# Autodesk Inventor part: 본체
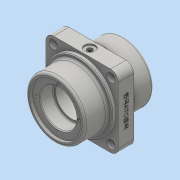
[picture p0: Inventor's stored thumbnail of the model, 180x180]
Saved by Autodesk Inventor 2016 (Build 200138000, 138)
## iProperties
Created: 2023-10
Part Number: 본체
Material: 일반
Document SubType Name: Modeling
Designer: pc-2
Density: 1 g/cm^3
Appearance: 기본값
Author: pc-2
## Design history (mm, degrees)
sketch "스케치1"
  geometry: L1 (47, -47)-(-47, -47); L2 (-47, -47)-(-47, 47); L3 (-47, 47)-(47, 47); L4 (47, 47)-(47, -47); L5 (47, -47)-(-47, 47); L6 (-47, -47)-(47, 47); 1 further point
  constraints: 12 end point, 2 midpoint, 2 parallel, 1 horizontal, 1 perpendicular
  dimensions: "d0" = 94 distance of L2.end L3.end; "d1" = 94 distance of L3.end L1.start
extrude "돌출1" new body sketch "스케치1" stored distance "d2" = 20; taper "d3" = 0 deg
sketch "스케치2"
  geometry: C1 r 44 at (0, 0); 1 further point
  constraints: 1 centre point, 1 coincident
  dimensions: "d4" = 88 diameter of C1
extrude "돌출2" join sketch "스케치2" distance "d5" = 5; taper "d6" = 0 deg
sketch "스케치3"
  geometry: C1 r 38 at (0, 0); 1 further point
  constraints: 1 centre point, 1 coincident
  dimensions: "d7" = 76 diameter of C1
extrude "돌출3" join sketch "스케치3" distance "d8" = 30; taper "d9" = 0 deg
hole "구멍1" diameter "d12" = 66; stored, may be unused: countersink angle "d16" = 90 deg, drill point angle "d18" = 0 deg; dims "d10" = 10, "d11" = 10, "d13" = 6, "d14" = 4, "d15" = 2, "d17" = 4
hole "구멍2" diameter "d21" = 47; stored, may be unused: countersink angle "d25" = 90 deg, drill point angle "d27" = 0 deg; dims "d19" = 10, "d20" = 10, "d22" = 6, "d23" = 4, "d24" = 2, "d26" = 17
hole "구멍3" diameter "d30" = 41; stored, may be unused: countersink angle "d34" = 90 deg, drill point angle "d36" = 0 deg; dims "d28" = 10, "d29" = 10, "d31" = 6, "d32" = 4, "d33" = 2, "d35" = 17
hole "구멍4" diameter "d39" = 14; stored, may be unused: countersink angle "d43" = 90 deg, drill point angle "d45" = 0 deg; dims "d37" = 10, "d38" = 47, "d40" = 82.55, "d41" = 4, "d42" = 2, "d44" = 2
hole "구멍5" diameter "d48" = 5.188; stored, may be unused: countersink angle "d52" = 90 deg, drill point angle "d54" = 0 deg; dims "d49" = 12, "d50" = 7, "d51" = 2, "d53" = 12, "d55" = 10, "d56" = 10
sketch "스케치4" dims "d57" = 54
  geometry: C1 r 33 at (0, 0) reference; 3 further points
  constraints: 1 coincident, 1 vertical alignment, 3 other
hole "구멍6" sketch "스케치4" at (0, 27) diameter "d58" = 3.242; stored, may be unused: countersink angle "d62" = 90 deg, drill point angle "d64" = 118 deg; dims "d59" = 8, "d60" = 4, "d61" = 2, "d63" = 10
fillet "모깎기1" dims "d68" = 10
sketch "스케치5" dims "d69" = 106
  geometry: L1 (0, 0)-(-54.91, -54.91); L2 (0, 0)-(0, -68.392); 2 further points
  constraints: 4 end point, 1 coincident, 1 point on line, 1 vertical, 3 other
  dimensions: "d70" = 45 deg angle of L2 L1
hole "구멍7" sketch "스케치5" at (-37.477, -37.477) diameter "d71" = 6.6; stored, may be unused: countersink angle "d75" = 90 deg, drill point angle "d77" = 0 deg; dims "d72" = 8, "d73" = 4, "d74" = 2, "d76" = 7
hole "구멍8" diameter "d80" = 11; stored, may be unused: countersink angle "d84" = 90 deg, drill point angle "d86" = 0 deg; dims "d78" = 10, "d79" = 10, "d81" = 8, "d82" = 4, "d83" = 2, "d85" = 7
fillet "모깎기2" dims "d90" = 3
fillet "모깎기3" dims "d91" = 3
fillet "모깎기4" dims "d92" = 3
fillet "모깎기5" dims "d93" = 1
chamfer "모따기1" distance "d94" = 1; stored, may be unused: second distance "d95" = 2, angle "d96" = 45 deg
chamfer "모따기2" distance "d97" = 1; stored, may be unused: second distance "d98" = 2, angle "d99" = 45 deg
sketch "스케치6"
  geometry: L1 (-61.5, 18.5)-(-12.5, 18.5); L2 (-12.5, 18.5)-(-12.5, 1.5); L3 (-12.5, 1.5)-(-61.5, 1.5); L4 (-61.5, 1.5)-(-61.5, 18.5); L5 (-61.5, 10)-(-12.5, 10); L6 (-37, 1.5)-(-37, 18.5); L7 (0, 0)-(-74, 0) reference; 2 further points
  constraints: 5 midpoint, 4 end point, 1 coincident, 2 other
  dimensions: "d100" = 49 distance of L1.start L1.end; "d101" = 17 distance of L1.end L2.end; "d102" = 10 distance between parallel lines of L5 L7
feature "엠보싱1" sketch "스케치6" dims "d0" = 94, "d1" = 94, "d103" = 0.5, "d104" = 0
node "솔리드1"
mirror "대칭1"
mirror "대칭2"
mirror "대칭3"
pattern_circular "원형 패턴1" dims angle "d66" = 360 deg
mirror "대칭4"
mirror "대칭5"
pattern_circular "원형 패턴2" dims "d88" = 360 deg
